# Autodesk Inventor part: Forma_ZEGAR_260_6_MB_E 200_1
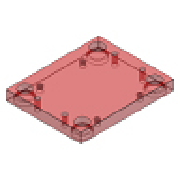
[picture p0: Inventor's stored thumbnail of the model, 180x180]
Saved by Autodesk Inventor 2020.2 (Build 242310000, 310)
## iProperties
Manager: www.cadconsulting.pl
Company: Fabian Stasiak CAD Consulting
IsCustomPart: 1
Created: 2014-02
Part Number: Forma_ZEGAR_260_6_MB_E 200_1
Material: S 55 C
Description: Core Plate
Document SubType Name: Modeling
Designer: F.Stasiak
Standard Revision: 1
Manufacturer: DME
Language: pl-PL
Size Designation: 496x346x46
Categories: <MemberInstance><Categories><Category DisplayName="Forma wtryskowa" InternalName="349578f2-f4d4-4954-8c09-8e99297a61c0" Mnemonic="MOLD"><Category DisplayName="P
Density: 7.85 g/cm^3
Appearance: Dark Red
Catalog Web Link: www.expertbooks.pl
Author: F.Stasiak
Subject: Zbiór ćwiczeń. Autodesk Inventor 2020. Kurs Professional
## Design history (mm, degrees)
sketch "Sketch1"
  geometry: L1 (-173, 248)-(173, 248); L2 (173, 248)-(173, -248); L3 (173, -248)-(-173, -248); L4 (-173, -248)-(-173, 248); 6 further points
  constraints: 8 end point, 2 midpoint, 2 parallel, 1 horizontal, 1 horizontal alignment, 1 perpendicular, 1 vertical alignment
  dimensions: "d123" = 346 distance between parallel lines of L2 L4 (= W_); "d124" = 496 distance between parallel lines of L3 L1 (= L); "d125" = 95 horizontal distance of point (0, 0) point (-95, 233) (= 0.5 x RP_W); "d126" = 233 vertical distance of point (0, 0) point (-95, 233) (= 0.5 x RP_L); "d127" = 137 horizontal distance of point (0, 0) point (-137, 208) (= 0.5 x GB_W); "d128" = 208 vertical distance of point (0, 0) point (-137, 208) (= 0.5 x GB_L); "d129" = 165 vertical distance of point (0, 0) point (-137, 165) (= 0.5 x S1_L); "d130" = 137 horizontal distance of point (0, 0) point (-137, 165) (= 0.5 x S1_W)
extrude "Extrusion1" new body sketch "Sketch1" distance "d20" = 46 (= H_); taper "d30" = 0 deg
hole "Hole1" sketch "Sketch1" diameter "d131" = 13.835; stored, may be unused: countersink angle "d135" = 90 deg, drill point angle "d137" = 118 deg; dims "d132" = 24.5 (= H_l), "d133" = 4, "d134" = 2, "d136" = 25 (= H_u)
pattern_linear "Rectangular Pattern1" dims "d140" = 330 (computed from S1_L, Ns), "d143" = 274 (computed from S1_W, Nw)
hole "Hole2" sketch "Sketch1" diameter "d144" = 42 (= GB_d1); stored, may be unused: countersink angle "d148" = 90 deg, drill point angle "d150" = 0 deg; dims "d145" = 6, "d146" = 48 (= GB_d2), "d147" = 6 (= GB_k), "d149" = 46 (= H_)
pattern_linear "Rectangular Pattern2" dims "d153" = 416 (computed from GB_L, Nl), "d156" = 274 (computed from GB_W, Nw)
hole "Hole3" sketch "Sketch1" diameter "d157" = 14 (= RP_dt); stored, may be unused: countersink angle "d161" = 90 deg, drill point angle "d163" = 0 deg; dims "d158" = 6, "d159" = 48 (= GB_d2), "d160" = 6 (= GB_k), "d162" = 46 (= H_)
pattern_linear "Rectangular Pattern3" dims "d166" = 466 (computed from RP_L, Nl), "d169" = 190 (computed from RP_W, Nw)
chamfer "Chamfer1" distance "d170" = 0.5; stored, may be unused: second distance "d171" = 2, angle "d172" = 45 deg
sketch "Szkic2"
  geometry: L1 (-78, -154.488)-(-78, 154.488); L2 (72.488, -160)-(-72.488, -160); L3 (78, 154.488)-(78, -154.488); L4 (-72.488, 160)-(72.488, 160); A1 r 4 centre (-75.879, 157.879) between (-72.488, 160) and (-78, 154.488); A2 r 4 centre (-75.879, -157.879) between (-78, -154.488) and (-72.488, -160); A3 r 4 centre (75.879, -157.879) between (72.488, -160) and (78, -154.488); A4 r 4 centre (75.879, 157.879) between (78, 154.488) and (72.488, 160)
  constraints: 8 end point, 8 point on circle, 4 centre point
extrude "Wyciągnięcie proste2" cut sketch "Szkic2" distance "d177" = 60; taper "d178" = 0 deg
sketch "Szkic3"
  geometry: 1 further point
hole "Otwór12" sketch "Szkic3" at (0, 0) diameter "d179" = 4.5; stored, may be unused: countersink angle "d183" = 90 deg, drill point angle "d185" = 0 deg; dims "d180" = 6, "d181" = 4, "d182" = 2, "d184" = 8
sketch "Szkic4"
  geometry: 4 further points
hole "Otwór13" sketch "Szkic4" at (-54, 134), (-24, -134), (24, 134), (54, -134) diameter "d186" = 5; stored, may be unused: countersink angle "d190" = 90 deg, drill point angle "d192" = 0 deg; dims "d187" = 6, "d188" = 4, "d189" = 2, "d191" = 8
sketch "Szkic5"
  geometry: 4 further points
hole "Otwór14" sketch "Szkic5" at (-24, 134), (-54, -134), (54, 134), (24, -134) diameter "d193" = 5; stored, may be unused: countersink angle "d197" = 90 deg, drill point angle "d199" = 0 deg; dims "d194" = 6, "d195" = 4, "d196" = 2, "d198" = 8
sketch "Szkic6"
  geometry: 4 further points
hole "Otwór15" sketch "Szkic6" at (-54, 103.5), (-24, -103.5), (24, 103.5), (54, -103.5) diameter "d200" = 5; stored, may be unused: countersink angle "d204" = 90 deg, drill point angle "d206" = 0 deg; dims "d201" = 6, "d202" = 4, "d203" = 2, "d205" = 8
sketch "Szkic7"
  geometry: 4 further points
hole "Otwór16" sketch "Szkic7" at (-24, 103.5), (-54, -103.5), (54, 103.5), (24, -103.5) diameter "d207" = 5; stored, may be unused: countersink angle "d211" = 90 deg, drill point angle "d213" = 0 deg; dims "d208" = 6, "d209" = 4, "d210" = 2, "d212" = 8
sketch "Szkic8"
  geometry: 4 further points
hole "Otwór17" sketch "Szkic8" at (-47, 71.2), (-31, -71.2), (31, 71.2), (47, -71.2) diameter "d214" = 5; stored, may be unused: countersink angle "d218" = 90 deg, drill point angle "d220" = 0 deg; dims "d215" = 6, "d216" = 4, "d217" = 2, "d219" = 8
sketch "Szkic9"
  geometry: 4 further points
hole "Otwór18" sketch "Szkic9" at (-31, 71.2), (-47, -71.2), (47, 71.2), (31, -71.2) diameter "d221" = 5; stored, may be unused: countersink angle "d225" = 90 deg, drill point angle "d227" = 0 deg; dims "d222" = 6, "d223" = 4, "d224" = 2, "d226" = 8
sketch "Szkic10"
  geometry: 4 further points
hole "Otwór19" sketch "Szkic10" at (-48.5, 54), (-29.5, -54), (29.5, 54), (48.5, -54) diameter "d228" = 5; stored, may be unused: countersink angle "d232" = 90 deg, drill point angle "d234" = 0 deg; dims "d229" = 6, "d230" = 4, "d231" = 2, "d233" = 8
sketch "Szkic11"
  geometry: 4 further points
hole "Otwór20" sketch "Szkic11" at (-29.5, 54), (-48.5, -54), (48.5, 54), (29.5, -54) diameter "d235" = 5; stored, may be unused: countersink angle "d239" = 90 deg, drill point angle "d241" = 0 deg; dims "d236" = 6, "d237" = 4, "d238" = 2, "d240" = 8
sketch "Szkic12"
  geometry: 4 further points
hole "Otwór21" sketch "Szkic12" at (-57, 29), (-21, -29), (21, 29), (57, -29) diameter "d242" = 5; stored, may be unused: countersink angle "d246" = 90 deg, drill point angle "d248" = 0 deg; dims "d243" = 6, "d244" = 4, "d245" = 2, "d247" = 8
sketch "Szkic13"
  geometry: 4 further points
hole "Otwór22" sketch "Szkic13" at (-39, 35), (-39, -35), (39, 35), (39, -35) diameter "d249" = 5; stored, may be unused: countersink angle "d253" = 90 deg, drill point angle "d255" = 0 deg; dims "d250" = 6, "d251" = 4, "d252" = 2, "d254" = 8
sketch "Szkic14"
  geometry: 4 further points
hole "Otwór23" sketch "Szkic14" at (-21, 29), (-57, -29), (57, 29), (21, -29) diameter "d256" = 5; stored, may be unused: countersink angle "d260" = 90 deg, drill point angle "d262" = 0 deg; dims "d257" = 6, "d258" = 4, "d259" = 2, "d261" = 8
node "Płaszczyzna konstrukcyjna6"
node "Punkt konstrukcyjny8"
node "Płaszczyzna konstrukcyjna7"
node "Punkt konstrukcyjny9"
node "Płaszczyzna konstrukcyjna8"
node "Punkt konstrukcyjny10"
node "Płaszczyzna konstrukcyjna9"
node "Punkt konstrukcyjny11"
feature "Rzeźbienie21"
feature "Rzeźbienie22"
feature "Rzeźbienie23"
feature "Rzeźbienie24"
feature "Rzeźbienie25"
feature "Rzeźbienie26"
feature "Rzeźbienie27"
feature "Rzeźbienie28"
feature "Rzeźbienie29"
feature "Rzeźbienie30"
feature "Rzeźbienie31"
feature "Rzeźbienie32"
feature "Rzeźbienie33"
feature "Rzeźbienie34"
feature "Rzeźbienie35"
feature "Rzeźbienie36"
feature "Rzeźbienie37"
feature "Rzeźbienie38"
feature "Rzeźbienie39"
feature "Rzeźbienie40"
feature "Rzeźbienie41"
feature "Rzeźbienie42"
node "Płaszczyzna konstrukcyjna10"
node "Płaszczyzna konstrukcyjna11"
body "Solid1"
feature "Powierzchnia21"
body "Srf21"
feature "Powierzchnia22"
body "Srf22"
feature "Powierzchnia23"
body "Srf23"
feature "Powierzchnia24"
body "Srf24"
feature "Powierzchnia25"
body "Srf25"
feature "Powierzchnia26"
body "Srf26"
feature "Powierzchnia27"
body "Srf27"
feature "Powierzchnia28"
body "Srf28"
feature "Powierzchnia29"
body "Srf29"
feature "Powierzchnia30"
body "Srf30"
feature "Powierzchnia31"
body "Srf31"
feature "Powierzchnia32"
body "Srf32"
feature "Powierzchnia33"
body "Srf33"
feature "Powierzchnia34"
body "Srf34"
feature "Powierzchnia35"
body "Srf35"
feature "Powierzchnia36"
body "Srf36"
feature "Powierzchnia37"
body "Srf37"
feature "Powierzchnia38"
body "Srf38"
feature "Powierzchnia39"
body "Srf39"
feature "Powierzchnia40"
body "Srf40"
feature "Powierzchnia41"
body "Srf41"
feature "Powierzchnia42"
body "Srf42"
other parameters: "L" = 496 [user parameter; used in 1 equation term], "W_" = 346 [user parameter; used in 1 equation term], "H_" = 46 [user parameter; used in 3 equation terms], "GB_W" = 274 [user parameter; used in 2 equation terms], "GB_d1" = 42 [user parameter; used in 1 equation term], "GB_d2" = 48 [user parameter; used in 2 equation terms], "GB_k" = 6 [user parameter; used in 2 equation terms], "S1_W" = 274 [user parameter; used in 2 equation terms], "RP_L" = 466 [user parameter; used in 2 equation terms], "RP_dt" = 14 [user parameter; used in 1 equation term], "GB_L" = 416 [user parameter; used in 2 equation terms], "le" = 24 [user parameter], "ke" = 33 [user parameter], "H_u" = 25 [user parameter; used in 1 equation term], "H_l" = 24.5 [user parameter; used in 1 equation term], "d176" = 25.8085, "d263" = 39, "d265" = 55.8085, "d266" = 0, "d267" = 0, "d268" = 0, "d269" = 39, "d271" = 55.8085, "d272" = 0, "d273" = 0, "d274" = -180 deg, "d275" = -39, "d277" = 55.8085, "d278" = 0, "d279" = 0, "d280" = 0, "d281" = -39, "d283" = 55.8085, "d284" = 0, "d285" = 0, "d286" = -180 deg, "d287" = 0, "d288" = 0, "d289" = 55.8085, "d290" = 0, "d291" = 0, "d292" = 0
